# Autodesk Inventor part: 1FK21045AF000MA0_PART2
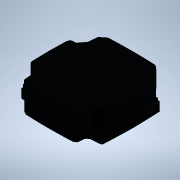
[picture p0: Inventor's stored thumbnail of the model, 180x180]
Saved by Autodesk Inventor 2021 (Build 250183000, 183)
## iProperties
Created: 2025-04
Part Number: 1FK21045AF000MA0_PART2
Material: Generic
Catalog Web Link: www.3dfindit.com
Description: -Servo synchronous motor
Document SubType Name: Modeling
Designer: psAdmin
Mass: 135.825 g
Surface Area: 188.795 cm^2
Volume: 135.825 cm^3
Density: 1 g/cm^3
Appearance: PSOLRGB-38-46-56
Category: PARTsolutions
Title: 1FK21045AF000MA0_PART2
Author: Cadenas PARTsolutions
Comments: Servo synchronous motor
Sending System: PARTsolutions
Preprocessor: ST-DEVELOPER v19.3
PSOL_IDENT_0: {$CADENAS_DATA/23d-libs/siemens_ag/_cat_/8b/0a/1fk21045af000ma0.prj},213 {VTYP=3D},{NB=1FK21045AF000
PSOL_IDENT_1: MA0_PART2},{LINA=1FK21045AF000MA0_PART2},{NN=1FK21045AF000MA0_PART2},{NOPRJ=TRUE},{DATE=19.08.2025 1
PSOL_IDENT_2: 4:00:48},{GEOMDATE=30.07.2025 02:00:28},{VERSION=},{LINEID=10},{WBVAR=},{WBNUMERIC=}  {NB=1FK21045AF
PSOL_IDENT_3: 000MA0_PART2},{LINA=1FK21045AF000MA0_PART2},{KT=DUMMY},{PREVIEW=../../../_pool_/a9/69/p_d211_xx_0081
PSOL_IDENT_4: 8j.png},{DESCSHORT=SIMOTICS S-1FK2 HD, SINAMICS S210 3AC 400V-480V, 2.4 Nm, 3000 rpm},{DESCLONG=SIMO
PSOL_IDENT_5: TICS S-1FK2 HD servo motor M0=2.4 Nm; PN = 0.75 kW at nN=3000 rpm (380-480 V); PN = 0.375 kW at nN=1
PSOL_IDENT_6: 500 rpm (200-240 V); degree of protection IP64; cylindrical shaft D19x40mm; absolute encoder 22-bit
PSOL_IDENT_7: + 12-bit multiturn (encoder AM22DQC); with OCC interface; plug size M17, rotatable; SIMOTICS S-1FK2
PSOL_IDENT_8: servomotorfor a wide range of uses in industrial environments. SIMOTICS S‑1FK2 servomotors are compa
PSOL_IDENT_9: ct synchronous motors with a high dynamic performance that set themselves apart as a result of their
PSOL_IDENT_10: high power density, degree of protection and overload capability. The motors are available in two v
PSOL_IDENT_11: ariants: as High Dynamic variant (highest dynamic performance as a result of the low intrinsic momen
PSOL_IDENT_12: t of inertia for applications demanding a high dynamic performance with low moved masses) - and as C
PSOL_IDENT_13: ompact variant (precise and stable closed-loop control for medium up to large moved masses as a resu
PSOL_IDENT_14: lt of a medium intrinsic moment of inertia). SIMOTICSS‑1FK2 servomotors fully exploit their strength
PSOL_IDENT_15: s in a system with the SINAMICSS210 frequency converter and simple connection using the one cable co
PSOL_IDENT_16: nnection (OCC). Advantages include the short control and positioning times, fast and precise correct
PSOL_IDENT_17: ion of disturbing quantities as well as stable control with a high dynamic performance. The servo mo
PSOL_IDENT_18: tors can be configured to address a wide range of requirements. For example with and without holding
PSOL_IDENT_19: brake, IP64 or IP65 degree of protection, singleturn or multiturn absolute encoders - to name just
PSOL_IDENT_20: a few. Further, the servomotors are available in different shaft heights extending from 20 to 100. A
PSOL_IDENT_21: shaft sealing ring is available to achieve an IP65 degree of protection and for subsequent mounting
PSOL_IDENT_22: at the motor or as spare part. SIMOTICS - the optimum motor for each and every motion control appli
PSOL_IDENT_23: cation.},{INTNO=195125050112},{SUPPLIERALTNO=1FK2104-5AF00-0MA0},{MANUID=1FK21045AF000MA0},{MANUNAME=
PSOL_IDENT_24: Siemens},{MANUTYPEDESC=Synchronous motor 1FK2-HD 2.4 NM},{AAU732=SIMOTICS},{AAO057=S-1FK2},{AAU734=S
PSOL_IDENT_25: IMOTICS S-1FK2 HD servo motor M0=2.4 Nm; PN = 0.75 kW at nN=3000 rpm (380-480 V); PN = 0.375 kW at n
PSOL_IDENT_26: N=1500 rpm (200-240 V); degree of protection IP64; cylindrical shaft D19x40mm; absolute encoder 22-b
PSOL_IDENT_27: it + 12-bit multiturn (encoder AM22DQC); with OCC interface; plug size M17, rotatable;},{AAW338=Sync
PSOL_IDENT_28: hronous motor 1FK2-HD 2.4 NM},{AAO742=SIMOTICS},{AAO663=4042948692912},{NOCUPEROU=1},{PRICEQUANTITY=
PSOL_IDENT_29: 1},{QUANTITYMIN=1},{QUANTITYINT=1},{CTN=85015100},{COO=DE},{AAO676=1FK2104-5AF00-0MA0},{AAO677=Sieme
PSOL_IDENT_30: ns AG},{ORDERUNIT=C62},{CONTENTUNIT=C62}
NB: 1FK21045AF000MA0_PART2
NT: Servo synchronous motor
NBSYN: $MANUID._PART2
LINA: 1FK21045AF000MA0_PART2
CATALOG: SIEMENS
PREVIEW: ../../../_pool_/a9/69/p_d211_xx_00818j.png
DESCSHORT: SIMOTICS S-1FK2 HD, SINAMICS S210 3AC 400V-480V, 2.4 Nm, 3000 rpm
DESCLONG: SIMOTICS S-1FK2 HD servo motor M0=2.4 Nm; PN = 0.75 kW at nN=3000 rpm (380-480 V); PN = 0.375 kW at nN=1500 rpm (200-240 V); degree of protection IP64; cylindri
INTNO: 195125050112
SUPPLIERALTNO: 1FK2104-5AF00-0MA0
MANUID: 1FK21045AF000MA0
MANUNAME: Siemens
MANUTYPEDESC: Synchronous motor 1FK2-HD 2.4 NM
AAU732: SIMOTICS
AAO057: S-1FK2
AAU734: SIMOTICS S-1FK2 HD servo motor M0=2.4 Nm; PN = 0.75 kW at nN=3000 rpm (380-480 V); PN = 0.375 kW at nN=1500 rpm (200-240 V); degree of protection IP64; cylindri
AAW338: Synchronous motor 1FK2-HD 2.4 NM
AAO742: SIMOTICS
AAO663: 4042948692912.0
NOCUPEROU: 1
PRICEQUANTITY: 1
QUANTITYMIN: 1
QUANTITYINT: 1
CTN: 85015100
COO: DE
ARTICLENO: 1FK21045AF000MA0_PART2
BOMINFO: 1FK21045AF000MA0_PART2
CREATOR: CADENAS GmbH
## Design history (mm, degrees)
feature "2025_04_17_15_40_42_0641"
body "Solid1"
